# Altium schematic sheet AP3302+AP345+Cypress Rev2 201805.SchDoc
size A4; CheckedBy: bao
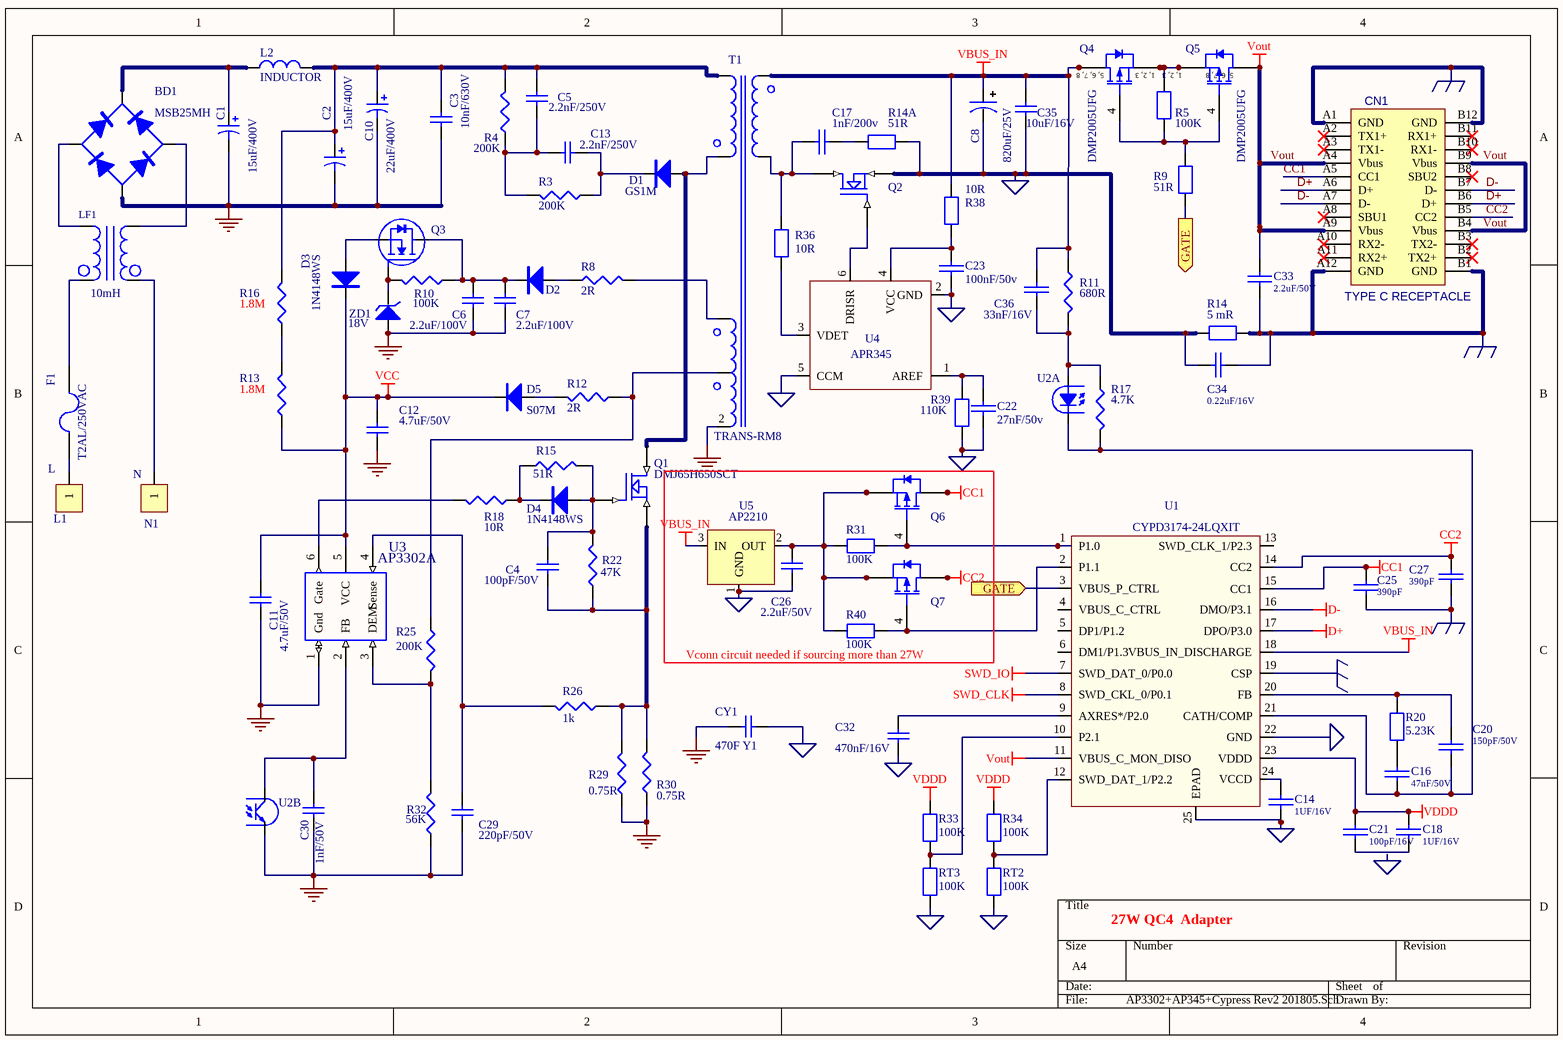
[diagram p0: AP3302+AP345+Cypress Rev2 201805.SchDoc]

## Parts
BD1  MSB25MH  [BD-MSBL2A_6.7*7.4]
C1  15uF/400V  [EC-8X16-P3.5-C]
C2  15uF/400V  [EC-8X16-P3.5-C]
C3  10nF/630V  [1206C(W)]
C4  100pF/50V  [0603C(W)]
C5  2.2nF/250V  [0805C(W)]
C6  2.2uF/100V  [1206C(w)]
C7  2.2uF/100V  [1206C(w)]
C8  820uF/25V  [EC-8X16-P3.5-C]
C10  22uF/400V  [EC-10X15-P5-C]
C11  4.7uF/50V  [1206C(W)]
C12  4.7uF/50V  [1206C(W)]
C13  2.2nF/250V  [0805C(W)]
C14  1UF/16V  [0603C(W)]
C16  47nF/50V  [0603C(W)]
C17  1nF/200v  [0805c(W)]
C18  1UF/16V  [0603C(W)]
C20  150pF/50V  [0603C(W)]
C21  100pF/16V  [0603C(W)]
C22  27nF/50v  [0603c(w)]
C23  100nF/50v  [0603c(w)]
C25  390pF  [0603C(W)]
C26  2.2uF/50V  [0603C(W)]
C27  390pF  [0603C(W)]
C29  220pF/50V  [0603C(W)]
C30  1nF/50V  [0603C(W)]
C32  470nF/16V  [0603C(W)]
C33  2.2uF/50V  [0805C(W)]
C34  0.22uF/16V  [0805C(W)]
C35  10uF/16V  [0805C(W)]
C36  33nF/16V  [0603c(w)]
CN1  TYPE C RECEPTACLE  [USB type C]
CY1  470F Y1  [YC-9.5X6-P10]
D1  GS1M  [SMD-(DO-214AC/SMA)]
D2  (no value)  [SMD-(SOD-123)]
D3  1N4148WS  [SMD-(SOD-523)]
D4  1N4148WS  [SMD-(SOD-523)]
D5  S07M  [SMD-(SOD-123)]
F1  T2AL/250VAC  [F-7.2X2.7-P5]
L1  L  [22#单线打端子]
L2  INDUCTOR  [L-D5-P2]
LF1  10mH  [LF-14.5X6.5-P7X5]
N1  N  [22#单线打端子]
Q1  DMJ65H650SCT  [TO-220-T型槽]
Q2  (no value)  [TO-220(DH)]
Q3  MOS-N2  [sot-23-1]  (value not drawn)
Q4  DMP2005UFG  [INF-PG-TSDSON-8-1_V]
Q5  DMP2005UFG  [INF-PG-TSDSON-8-1_V]
Q6  DMP2005UFG  [INF-PG-TSDSON-8-1_V]  (value not drawn)
Q7  DMP2005UFG  [INF-PG-TSDSON-8-1_V]  (value not drawn)
R3  200K  [1206(W)]
R4  200K  [1206(W)]
R5  100K  [0402(W)]
R8  2R  [0603(W)]
R9  51R  [0603(W)]
R10  100K  [0603(w)]
R11  680R  [0603(W)]
R12  2R  [0603(W)]
R13  1.8M  [1206(W)]
R14  5 mR  [1206(W)]
R14A  51R  [1206(w)]
R15  51R  [0805(W)]
R16  1.8M  [1206(W)]
R17  4.7K  [0402(W)]
R18  10R  [0805(W)]
R20  5.23K  [0402(W)]
R22  47K  [0603(W)]
R25  200K  [0805(W)]
R26  1k  [0603(W)]
R29  0.75R  [1206(W)]
R30  0.75R  [1206(W)]
R31  100K  [0603(w)]
R32  56K  [0603(W)]
R33  100K  [0402(W)]
R34  100K  [0402(W)]
R36  10R  [0603(w)]
R38  10R  [0603(W)]
R39  110K  [0603(w)]
R40  100K  [0603(w)]
RT2  100K  [0402(W)]
RT3  100K  [0402(W)]
T1  TRANS-RM8  [TF-RM8(PIN6+2)]
U1  CYPD3174-24LQXIT
U2  PC-4PIN  [SO-4(P10) - photocoupler]  (value not drawn)  (parts A,B of 2)
U3  AP3302A  [SOT-23-6]
U4  APR345  [SOT-23-6]
U5  AP2210  [D-46_6A]
ZD1  18V  [SMD-(SOD-523)]

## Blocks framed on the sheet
Vconn circuit needed if sourcing more than 27W: C26 Q6 Q7 R31 R40 U5

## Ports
GATE

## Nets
CC1: C25.2 CN1.A5(CC1) Q6.5(DRAIN) Q6.6(DRAIN) Q6.7(DRAIN) Q6.8(DRAIN) U1.15(CC1)
CC2: C27.2 CN1.B5(CC2) Q7.5(DRAIN) Q7.6(DRAIN) Q7.7(DRAIN) Q7.8(DRAIN) U1.14(CC2)
D+: CN1.A6(D+) CN1.B6(D+) U1.17(DPO/P3.0)
D-: CN1.A7(D-) CN1.B7(D-) U1.16(DMO/P3.1)
EARTH: C25.1 C27.1 C33.2 C34.2 CN1.A1(GND) CN1.A12(GND) CN1.B1(GND) CN1.B12(GND) R14.1 U1.19(CSP)
GND: BD1.4 C1.2 C2.2 C3.1 C6.1 C7.1 C10.2 C11.1 C12.1 C29.1 C30.1 CY1.2 R29.1 R30.1 R32.1 T1.2 U2.3 U3.1(Gnd) ZD1.1(A)
SGND: C8.2 C14.1 C22.1 C23.1 C26.1 C32.1 C34.1 C35.1 CY1.1 Q2.3(S) R14.2 R14A.1 R39.1 RT2.2 RT3.2 U1.22(GND) U1.25(EPAD) U4.2(GND) U4.5(CCM) U5.1(GND)
SWD_CLK: U1.8(SWD_CKL_0/P0.1)
SWD_IO: U1.7(SWD_DAT_0/P0.0)
VBUS_IN: C8.1 C35.2 C36.2 Q4.5(DRAIN) Q4.6(DRAIN) Q4.7(DRAIN) Q4.8(DRAIN) R11.1 R38.1 T1.8 U1.18(VBUS_IN_DISCHARGE) U5.3(IN)
VCC: C11.2 C12.2 D3.2 D5.2 R13.1 U3.5(VCC)
VDDD: C18.2 C21.2 R33.1 R34.1 U1.23(VDDD)
Vout: C33.1 CN1.A4(Vbus) CN1.A9(Vbus) CN1.B4(Vbus) CN1.B9(Vbus) Q5.5(DRAIN) Q5.6(DRAIN) Q5.7(DRAIN) Q5.8(DRAIN) U1.11(VBUS_C_MON_DISO)
GATE: R9.1 U1.3(VBUS_P_CTRL) ; port GATE
NetBD1_1: BD1.1 C1.1 L2.1
NetBD1_2: BD1.2 LF1.2
NetBD1_3: BD1.3 LF1.3
NetC2_1: C2.1 C3.2 C5.2 C10.1 L2.2 R4.1 R16.2 T1.1
NetC4_1: C4.1 Q1.3(S) R22.1 R26.1 R29.2 R30.2
NetC4_2: C4.2 D4.1 Q1.1(G) R15.2 R22.2
NetC5_1: C5.1 C13.2 R3.1 R4.2
NetC6_2: C6.2 C7.2 D2.2 Q3.2(D) R10.1
NetC13_1: C13.1 D1.2 R3.2
NetC14_2: C14.2 U1.24(VCCD)
NetC16_1: C16.1 C20.1 R17.2 U1.21(CATH/COMP) U2.2
NetC16_2: C16.2 R20.2
NetC17_1: C17.1 Q2.2(D) R36.1 T1.7
NetC17_2: C17.2 R14A.2
NetC18_1: C18.1 C21.1
NetC20_2: C20.2 R20.1 U1.20(FB)
NetC22_2: C22.2 R39.2 U4.1(AREF)
NetC23_2: C23.2 R38.2 U4.4(VCC)
NetC26_2: C26.2 Q6.1(SOURCE) Q6.2(SOURCE) Q6.3(SOURCE) Q7.1(SOURCE) Q7.2(SOURCE) Q7.3(SOURCE) R31.2 R40.2 U5.2(OUT)
NetC29_2: C29.2 R26.2 U3.4(Sense)
NetC30_2: C30.2 U2.4 U3.2(FB)
NetC32_2: C32.2 U1.9(AXRES*/P2.0)
NetC36_1: C36.1 R11.2 R17.1 U2.1
NetD1_1: D1.1 Q1.2(D) T1.5
NetD2_1: D2.1 R8.1
NetD3_1: D3.1 Q3.3(S)
NetD4_2: D4.2 R15.1 R18.1
NetD5_1: D5.1 R12.2
NetF1_1: F1.1 LF1.1
NetF1_2: F1.2 L1.1
NetLF1_4: LF1.4 N1.1
NetQ2_1: Q2.1(G) U4.6(DRISR)
NetQ3_1: Q3.1(G) R10.2 ZD1.2(K)
NetQ4_1: Q4.1(SOURCE) Q4.2(SOURCE) Q4.3(SOURCE) Q5.1(SOURCE) Q5.2(SOURCE) Q5.3(SOURCE) R5.1
NetQ4_4: Q4.4(GATE) Q5.4(GATE) R5.2 R9.2
NetQ6_4: Q6.4(GATE) R31.1 U1.1(P1.0)
NetQ7_4: Q7.4(GATE) R40.1 U1.2(P1.1)
NetR8_2: R8.2 T1.6
NetR12_1: R12.1 R25.1 T1.4
NetR13_2: R13.2 R16.1
NetR18_2: R18.2 U3.6(Gate)
NetR25_2: R25.2 R32.2 U3.3(DEM)
NetR33_2: R33.2 RT3.1 U1.10(P2.1)
NetR34_2: R34.2 RT2.1 U1.12(SWD_DAT_1/P2.2)
NetR36_2: R36.2 U4.3(VDET)

Not connected (* = marked no-connect by the designer): CN1 A2(TX1+)* A3(TX1-)* A8(SBU1)* A10(RX2-)* A11(RX2+)* B2(TX2+)* B3(TX2-)* B8(SBU2)* B10(RX1-)* B11(RX1+)*; U1 4(VBUS_C_CTRL) 5(DP1/P1.2) 6(DM1/P1.3) 13(SWD_CLK_1/P2.3)

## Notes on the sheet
- 27W QC4  Adapter
- Labels drawn without touching a wire or pin: SGND

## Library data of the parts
BD1 = BRIDGE: Diode
C1 C2 C10 = Cap Pol1: Polarized Capacitor (Radial); Value: 100pF
C3-C7 C11-C13 C26 C29 C30 C32 C35 CY1 = Cap: Capacitor; Value: 100pF
C8 = CAPACITOR
C14 C16-C18 C20-C23 C25 C27 C33 C34 C36 = CAP: Capacitor
CN1 = USB TYPE-C
D1-D5 = D: Diode
F1 = Fuse 2: Fuse
L1 N1 = CON1: Connector
LF1 = INDUCTOR IRON
Q1 Q2 = MOSFET N
Q3 = MOS-N2: MOS
Q4-Q7 = BSZ086P03NS3 G: P-Channel OptiMOS P3 Power-Transistor, -30 V VDS, -40 A ID, -55 to 150 degC, PG-TSDSON-8-1, Reel, Green; Manufacturer: Infineon; Green: TRUE; ID (max): -40 A; IDpuls (max): -160 A; Pto t (max): 69 W; QG: 43.2 nC; RDS (on) (max): 8.6 mOhm; Rth: 1.8 K/W; RthJC (max): 1.8 K/W; VDS (max): -30 V; VGS(th) (max): -1.9 V; VGS(th) (min): -3.1 V
R3 R4 R8 R10-R13 R15-R18 R22 R25 R29 R30 R32 = Res3: Resistor; Value: 1K
R5 R9 R14 R14A R20 R31 R33 R34 R36 R38-R40 RT2 RT3 = RES2
R26 = Res3: Resistor
T1 = TRANS_RM7: transformer
U1 = Component_2
U2 = PC-4PIN: Optical coupling
U3 = IC_SG6848T
U4 = AP345
U5 = Bridge2: Diode Bridge
ZD1 = ZD: Zener Diode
